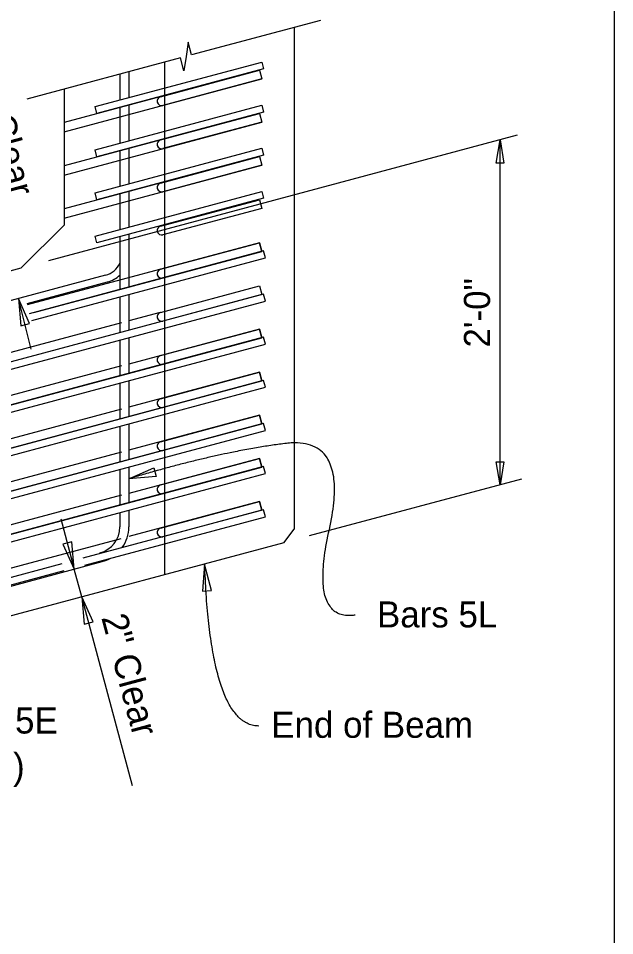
# Model space of a CAD drawing. Extents: x 120700.3 to 120754.4, y 120608.4 to 120631.3.
# Drawn here: x 120727.62 to 120731.07, y 120614.68 to 120620 of the extents above; entities that cross this region are included whole.
import ezdxf

# ---------------------------------------------------------------- set-up
doc = ezdxf.new("R2010")
doc.units = 0
for name, color, linetype in [('ActivePts-ConstElements', 7, 'Continuous'), ('BeamConc', 7, 'Continuous'), ('BeamConc_h', 7, 'Continuous'), ('Dimension', 7, 'Continuous'), ('Rebar', 7, 'Continuous'), ('Rebar_h', 7, 'Continuous'), ('TextStructures', 7, 'Continuous')]:
    doc.layers.add(name, color=color, linetype=linetype)

msp = doc.modelspace()

# ---------------------------------------------------------------- linework, layer by layer
at = {"layer": 'ActivePts-ConstElements'}
msp.add_lwpolyline([(120700.2847, 120610.4195), (120731.0726, 120610.4195), (120731.0726, 120629.8791), (120700.2847, 120629.8791)], close=True, dxfattribs=at)
at = {"layer": 'BeamConc'}
for p, q in [((120729.2163, 120619.943), (120729.2163, 120617.0341)), ((120727.8829, 120619.5858), (120727.8829, 120618.7974)), ((120727.8829, 120618.7974), (120727.6329, 120618.5474)), ((120727.6329, 120618.5474), (120726.5616, 120618.2603)), ((120729.1559, 120616.9555), (120729.2163, 120617.0341)), ((120729.1559, 120616.9555), (120721.7359, 120614.9673))]:
    msp.add_line(p, q, dxfattribs=at)
at = {"layer": 'BeamConc_h'}
msp.add_line((120728.4662, 120616.7707), (120728.4662, 120619.7421), dxfattribs=at)
at = {"layer": 'Dimension'}
for p, q in [((120730.5087, 120619.3179), (120727.7919, 120618.59)), ((120730.4085, 120617.2911), (120730.4085, 120619.2911)), ((120727.6243, 120618.5451), (120727.6243, 120618.5451)), ((120727.6928, 120618.0775), (120727.6185, 120618.3709)), ((120727.6674, 120618.384), (120727.6674, 120618.384)), ((120730.532, 120617.3242), (120729.3031, 120616.9949)), ((120727.8635, 120617.0948), (120727.9418, 120616.8027)), ((120727.9849, 120616.6417), (120727.9418, 120616.8027)), ((120728.0148, 120616.8222), (120728.0149, 120616.8222)), ((120728.2785, 120615.5462), (120727.9849, 120616.6417)), ((120727.9119, 120616.6221), (120727.9119, 120616.6221))]:
    msp.add_line(p, q, dxfattribs=at)
msp.add_lwpolyline([(120729.3675, 120619.9835), (120728.6218, 120619.7838), (120728.6018, 120619.8585), (120728.5893, 120619.775), (120728.5766, 120619.6914), (120728.5566, 120619.7663), (120727.6669, 120619.5279)], dxfattribs=at)
for points in [[(120730.4084, 120619.2909), (120730.4305, 120619.1571), (120730.3863, 120619.1571)], [(120727.6185, 120618.3709), (120727.6312, 120618.213), (120727.6825, 120618.226)], [(120728.2579, 120617.3266), (120728.4029, 120617.3905), (120728.4158, 120617.3391)], [(120730.4084, 120617.2909), (120730.3863, 120617.4246), (120730.4305, 120617.4246)], [(120727.9418, 120616.8027), (120727.9269, 120616.9604), (120727.8758, 120616.9467)], [(120728.6971, 120616.8324), (120728.6842, 120616.6746), (120728.7369, 120616.6791)], [(120727.9849, 120616.6417), (120727.9998, 120616.484), (120728.0509, 120616.4976)]]:
    msp.add_lwpolyline(points, close=True, dxfattribs=at)
for points in [[(120729.5685, 120616.5361), (120729.3, 120616.4965), (120729.5402, 120617.5762), (120728.7942, 120617.4864), (120728.2579, 120617.3267)], [(120729.0114, 120615.8933), (120728.7309, 120615.8933), (120728.6971, 120616.8325)]]:
    msp.add_open_spline(points, degree=2, dxfattribs=at)
at = {"layer": 'Rebar'}
for p, q in [((120728.062, 120619.4838), (120729.028, 120619.7427)), ((120729.028, 120619.7427), (120729.0388, 120619.7024)), ((120729.0388, 120619.7024), (120728.0728, 120619.4436)), ((120728.2058, 120619.6723), (120728.2058, 120619.5224)), ((120728.2579, 120619.6863), (120728.2579, 120619.5363)), ((120728.4411, 120619.5409), (120729.0149, 120619.6946)), ((120729.0149, 120619.6946), (120729.0284, 120619.6443)), ((120729.0284, 120619.6443), (120728.4546, 120619.4906)), ((120728.062, 120619.2338), (120729.028, 120619.4927)), ((120728.0728, 120619.4436), (120728.062, 120619.4838)), ((120729.0388, 120619.4524), (120728.0728, 120619.1936)), ((120728.2058, 120619.4792), (120728.2058, 120619.2724)), ((120728.2579, 120619.4932), (120728.2579, 120619.2863)), ((120729.028, 120619.4927), (120729.0388, 120619.4524)), ((120728.4411, 120619.2909), (120729.0149, 120619.4446)), ((120729.0149, 120619.4446), (120729.0284, 120619.3943)), ((120729.0284, 120619.3943), (120728.4546, 120619.2406)), ((120728.062, 120618.9838), (120729.028, 120619.2427)), ((120728.2579, 120619.2432), (120728.2579, 120619.0363)), ((120729.028, 120619.2427), (120729.0388, 120619.2024)), ((120728.0728, 120619.1936), (120728.062, 120619.2338)), ((120729.0388, 120619.2024), (120728.0728, 120618.9436)), ((120728.2058, 120619.2292), (120728.2058, 120619.0224)), ((120728.4411, 120619.0409), (120729.0149, 120619.1946)), ((120729.0149, 120619.1946), (120729.0284, 120619.1443)), ((120729.0284, 120619.1443), (120728.4546, 120618.9906)), ((120728.062, 120618.7338), (120729.028, 120618.9927)), ((120728.0728, 120618.9436), (120728.062, 120618.9838)), ((120728.2058, 120618.9792), (120728.2058, 120618.7724)), ((120728.2579, 120618.9932), (120728.2579, 120618.7863)), ((120729.028, 120618.9927), (120729.0388, 120618.9524)), ((120729.0388, 120618.9524), (120728.0728, 120618.6936)), ((120728.4411, 120618.7909), (120729.0149, 120618.9446)), ((120729.0149, 120618.9446), (120729.0284, 120618.8943)), ((120729.0284, 120618.8943), (120728.4546, 120618.7406)), ((120728.0728, 120618.6936), (120728.062, 120618.7338)), ((120728.2058, 120618.7292), (120728.2058, 120618.4239)), ((120728.2579, 120618.7432), (120728.2579, 120618.4379)), ((120728.4411, 120618.5409), (120729.0149, 120618.6946)), ((120729.0149, 120618.6946), (120729.0284, 120618.6443)), ((120729.0388, 120618.6471), (120727.681, 120618.2833)), ((120727.696, 120618.2442), (120729.0496, 120618.6068)), ((120729.0284, 120618.6443), (120728.4546, 120618.4906)), ((120729.0496, 120618.6068), (120729.0388, 120618.6471)), ((120728.1236, 120618.5063), (120723.9872, 120617.3979)), ((120727.6687, 120618.3427), (120728.1344, 120618.4675)), ((120728.4411, 120618.2909), (120729.0149, 120618.4446)), ((120729.0149, 120618.4446), (120729.0284, 120618.3943)), ((120729.0388, 120618.3971), (120720.9246, 120616.2229)), ((120728.2579, 120618.3947), (120728.2579, 120618.1879)), ((120729.0284, 120618.3943), (120728.4546, 120618.2406)), ((120729.0496, 120618.3568), (120729.0388, 120618.3971)), ((120720.9354, 120616.1826), (120729.0496, 120618.3568)), ((120728.2058, 120618.3807), (120728.2058, 120618.1739)), ((120728.4411, 120618.0409), (120729.0149, 120618.1946)), ((120729.0149, 120618.1946), (120729.0284, 120618.1443)), ((120729.0388, 120618.1471), (120726.6798, 120617.515)), ((120728.2058, 120618.1307), (120728.2058, 120617.9239)), ((120728.2579, 120618.1447), (120728.2579, 120617.9379)), ((120729.0284, 120618.1443), (120728.4546, 120617.9906)), ((120729.0496, 120618.1068), (120729.0388, 120618.1471)), ((120726.6798, 120617.4719), (120729.0496, 120618.1068)), ((120728.4411, 120617.7909), (120729.0149, 120617.9446)), ((120729.0149, 120617.9446), (120729.0284, 120617.8943)), ((120729.0388, 120617.8971), (120726.6798, 120617.265)), ((120726.6798, 120617.2219), (120729.0496, 120617.8568)), ((120728.2058, 120617.8807), (120728.2058, 120617.6739)), ((120728.2579, 120617.8947), (120728.2579, 120617.6879)), ((120729.0284, 120617.8943), (120728.4546, 120617.7406)), ((120729.0496, 120617.8568), (120729.0388, 120617.8971)), ((120729.0388, 120617.6471), (120726.6652, 120617.0111)), ((120728.2579, 120617.6447), (120728.2579, 120617.4379)), ((120728.4411, 120617.5409), (120729.0149, 120617.6946)), ((120729.0284, 120617.6443), (120728.4546, 120617.4906)), ((120729.0149, 120617.6946), (120729.0284, 120617.6443)), ((120729.0496, 120617.6068), (120729.0388, 120617.6471)), ((120726.6798, 120616.9719), (120729.0496, 120617.6068)), ((120728.2058, 120617.6307), (120728.2058, 120617.4239)), ((120728.4411, 120617.2909), (120729.0149, 120617.4446)), ((120729.0149, 120617.4446), (120729.0284, 120617.3943)), ((120729.0388, 120617.3971), (120726.6825, 120616.7657)), ((120728.2058, 120617.3807), (120728.2058, 120617.1739)), ((120728.2579, 120617.3947), (120728.2579, 120617.1879)), ((120729.0284, 120617.3943), (120728.4546, 120617.2406)), ((120729.0496, 120617.3568), (120729.0388, 120617.3971)), ((120726.6798, 120616.7219), (120729.0496, 120617.3568)), ((120728.4411, 120617.0409), (120729.0149, 120617.1946)), ((120729.0149, 120617.1946), (120729.0284, 120617.1443)), ((120729.0388, 120617.1471), (120727.991, 120616.8663)), ((120728.2058, 120617.1308), (120728.2058, 120617.0473)), ((120728.2579, 120617.1447), (120728.2579, 120617.0473)), ((120729.0284, 120617.1443), (120728.4546, 120616.9906)), ((120729.0496, 120617.1068), (120729.0388, 120617.1471)), ((120728.002, 120616.8261), (120729.0496, 120617.1068)), ((120721.9785, 120615.2049), (120728.1035, 120616.8461)), ((120727.8702, 120616.834), (120720.9246, 120614.9729)), ((120720.9354, 120614.9326), (120727.8827, 120616.7942))]:
    msp.add_line(p, q, dxfattribs=at)
msp.add_lwpolyline([(120726.6798, 120617.2651), (120729.0283, 120617.8944), (120729.0149, 120617.9446), (120728.2579, 120617.7418)], dxfattribs=at)
for centre, radius, start, end in [((120728.4479, 120619.5157), 0.026, 105, 285), ((120728.4479, 120619.2657), 0.026, 105, 285), ((120728.4479, 120619.0157), 0.026, 105, 285), ((120728.4479, 120618.7657), 0.026, 105, 285), ((120728.0913, 120618.627), 0.125, 285, 336.4435), ((120728.0912, 120618.6285), 0.1667, 285, 313.4375), ((120728.4479, 120618.5157), 0.026, 105, 285), ((120728.4479, 120618.2657), 0.026, 105, 285), ((120728.4479, 120618.0157), 0.026, 105, 285), ((120728.4479, 120617.7657), 0.026, 105, 285), ((120728.4479, 120617.5157), 0.026, 105, 285), ((120728.4479, 120617.2657), 0.026, 105, 285), ((120728.0496, 120617.0473), 0.1562, 285, 360), ((120728.0496, 120617.0473), 0.2083, 324.9903, 360), ((120728.4479, 120617.0157), 0.026, 105, 285), ((120728.0496, 120617.0473), 0.2083, 285, 299.9388)]:
    msp.add_arc(centre, radius, start, end, dxfattribs=at)
at = {"layer": 'Rebar_h'}
for p, q in [((120729.0149, 120619.6946), (120727.8829, 120619.3913)), ((120727.8829, 120619.3374), (120729.0283, 120619.6444)), ((120729.0149, 120619.4446), (120727.8829, 120619.1413)), ((120727.8829, 120619.0874), (120729.0283, 120619.3944)), ((120729.0149, 120619.1946), (120727.8829, 120618.8913)), ((120727.8829, 120618.8374), (120729.0283, 120619.1444)), ((120729.0149, 120618.6946), (120727.6689, 120618.334)), ((120729.0283, 120618.6444), (120729.0149, 120618.6946)), ((120727.707, 120618.2903), (120729.0283, 120618.6444)), ((120729.0149, 120617.1946), (120728.2579, 120616.9918)), ((120729.0283, 120617.1444), (120729.0149, 120617.1946)), ((120728.2114, 120616.9793), (120726.0131, 120616.3903))]:
    msp.add_line(p, q, dxfattribs=at)
for points in [[(120728.4399, 120618.2905), (120728.2579, 120618.2418)], [(120728.2163, 120618.2306), (120721.7579, 120616.5001)], [(120726.6798, 120617.5151), (120729.0283, 120618.1444), (120729.0149, 120618.1946), (120728.2579, 120617.9918)], [(120728.2163, 120617.9806), (120721.7579, 120616.2501)], [(120728.2163, 120617.7306), (120726.6798, 120617.3189)], [(120726.6798, 120617.0151), (120729.0283, 120617.6444), (120729.0149, 120617.6946), (120728.2579, 120617.4918)], [(120728.2163, 120617.4806), (120726.6798, 120617.0689)], [(120726.6798, 120616.7651), (120729.0283, 120617.3944), (120729.0149, 120617.4446), (120728.2579, 120617.2418)], [(120728.2163, 120617.2306), (120727.0131, 120616.9082)]]:
    msp.add_lwpolyline(points, dxfattribs=at)

# ---------------------------------------------------------------- texts
at = {"layer": 'Dimension'}
for s, p in [('Bars 5E ', (120727.1267, 120615.8496)), ('(Typ.)', (120727.1267, 120615.5856))]:
    msp.add_text(s, height=0.1512, dxfattribs=at).set_placement(p)
at = {"layer": 'TextStructures'}
for s, rotation, p in [('2" Clear', 285, (120727.381, 120619.6526)), ('2\'-0"', 90, (120730.3506, 120618.0873)), ('2" Clear', 285, (120728.0975, 120616.5222))]:
    msp.add_text(s, height=0.1512, rotation=rotation, dxfattribs=at).set_placement(p)
for s, p in [('Bars 5L', (120729.6958, 120616.4648)), ('End of Beam', (120729.0833, 120615.8249))]:
    msp.add_text(s, height=0.1512, dxfattribs=at).set_placement(p)

doc.saveas('drawing.dxf')
